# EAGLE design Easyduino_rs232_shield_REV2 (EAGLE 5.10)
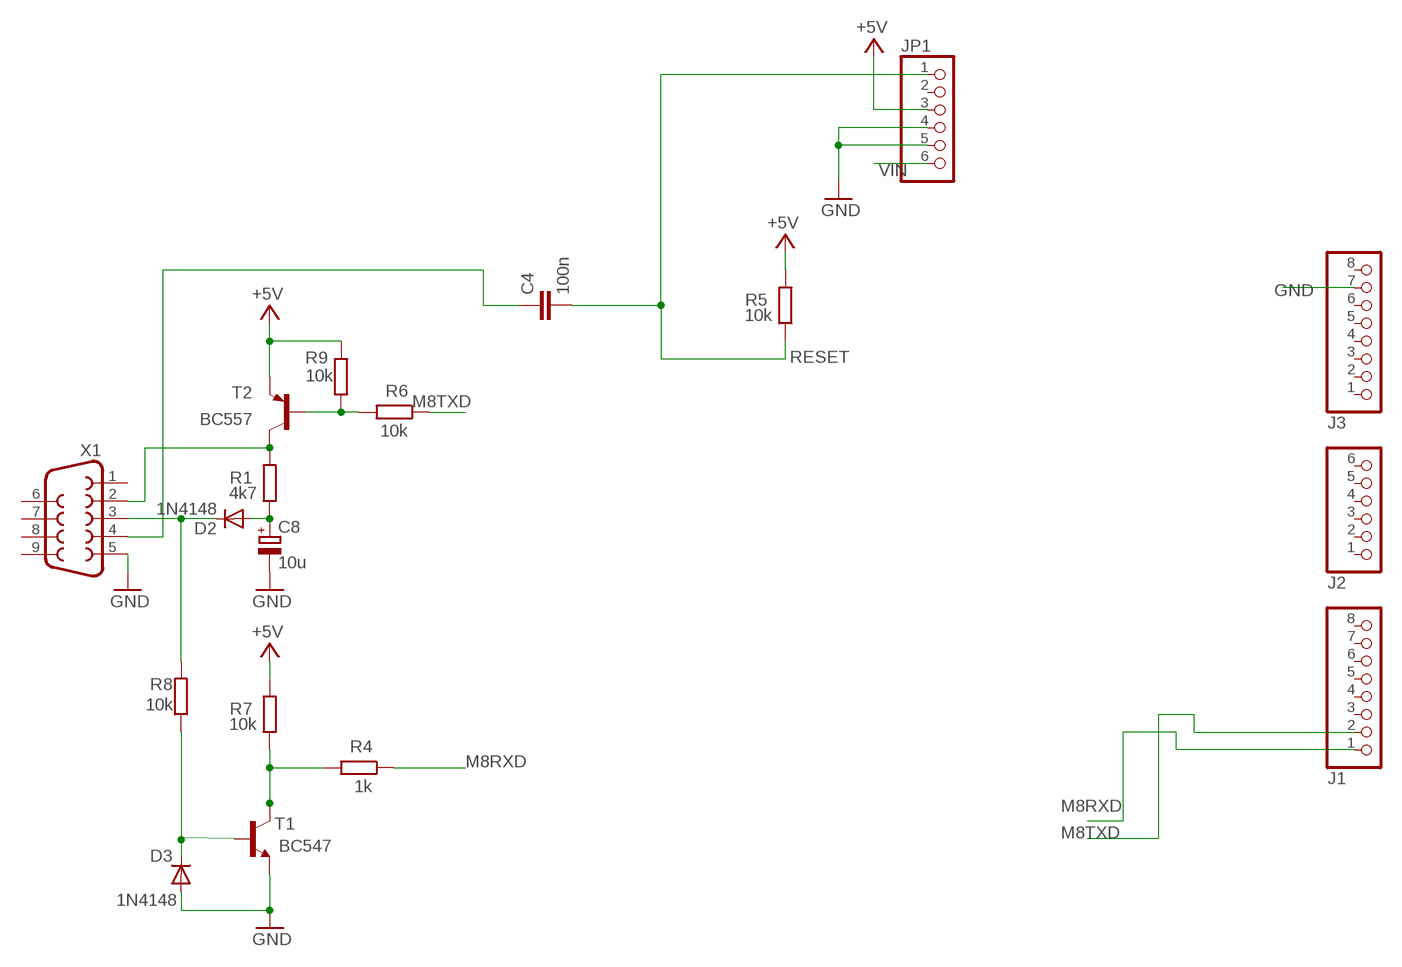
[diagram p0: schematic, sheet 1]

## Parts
C4  100n  C-EU050-025X075  [C050-025X075]
C8  10u  CPOL-EUE5-6  [E5-6]
D2  1N4148  [DO35-10]
D3  1N4148  [DO35-10]
J1  PINHD-1X8  [1X08]
J2  PINHD-1X6  [1X06]
J3  PINHD-1X8  [1X08]
JP1  PINHD-1X6  [1X06]
R1  4k7  R-EU_0207/10  [0207/10]
R4  1k  R-EU_0207/10  [0207/10]
R5  10k  R-EU_0207/10  [0207/10]
R6  10k  R-EU_0207/10  [0207/10]
R7  10k  R-EU_0207/10  [0207/10]
R8  10k  R-EU_0207/10  [0207/10]
R9  10k  R-EU_0207/10  [0207/10]
T1  BC547  [TO92]
T2  BC557  BC557B-PNP-TO92-EBC  [TO92-EBC]
X1  F09H  [F09H]

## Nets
+5V [power]: JP1.3 R5.2 R7.2 R9.1 T2.E
GND [power]: C8.- D3.A J3.7 JP1.4 JP1.5 T1.1(E) X1.5
M8RXD: J1.1 R4.1
M8TXD: J1.2 R6.1
N$9: R1.2 T2.C X1.2
N$24: C8.+ D2.A R1.1
N$25: D2.C R8.2 X1.3
N$26: R4.2 R7.1 T1.3(C)
N$27: R6.2 R9.2 T2.B
N$28: C4.1 X1.4
N$29: D3.C R8.1 T1.2(B)
RESET: C4.2 JP1.1 R5.1
VIN [power]: JP1.6
Unconnected: J1.3 J1.4 J1.5 J1.6 J1.7 J1.8 J2.1 J2.2 J2.3 J2.4 J2.5 J2.6 J3.1 J3.2 J3.3 J3.4 J3.5 J3.6 J3.8 JP1.2 X1.1 X1.6 X1.7 X1.8 X1.9

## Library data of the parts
C4 = rcl:C-EU: CAPACITOR, European symbol
C8 = rcl:CPOL-EU: POLARIZED CAPACITOR, European symbol
D2 D3 = diode:1N4148: DIODE
J1 J3 = pinhead:PINHD-1X8: PIN HEADER
J2 JP1 = pinhead:PINHD-1X6: PIN HEADER
R1 R4-R9 = rcl:R-EU_: RESISTOR, European symbol
T1 = transistor:BC547: NPN TRANSISTOR
T2 = transistor:*-PNP-: PNP Transistror
X1 = con-subd:F09: SUB-D

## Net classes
1 power: width 0.61 mm

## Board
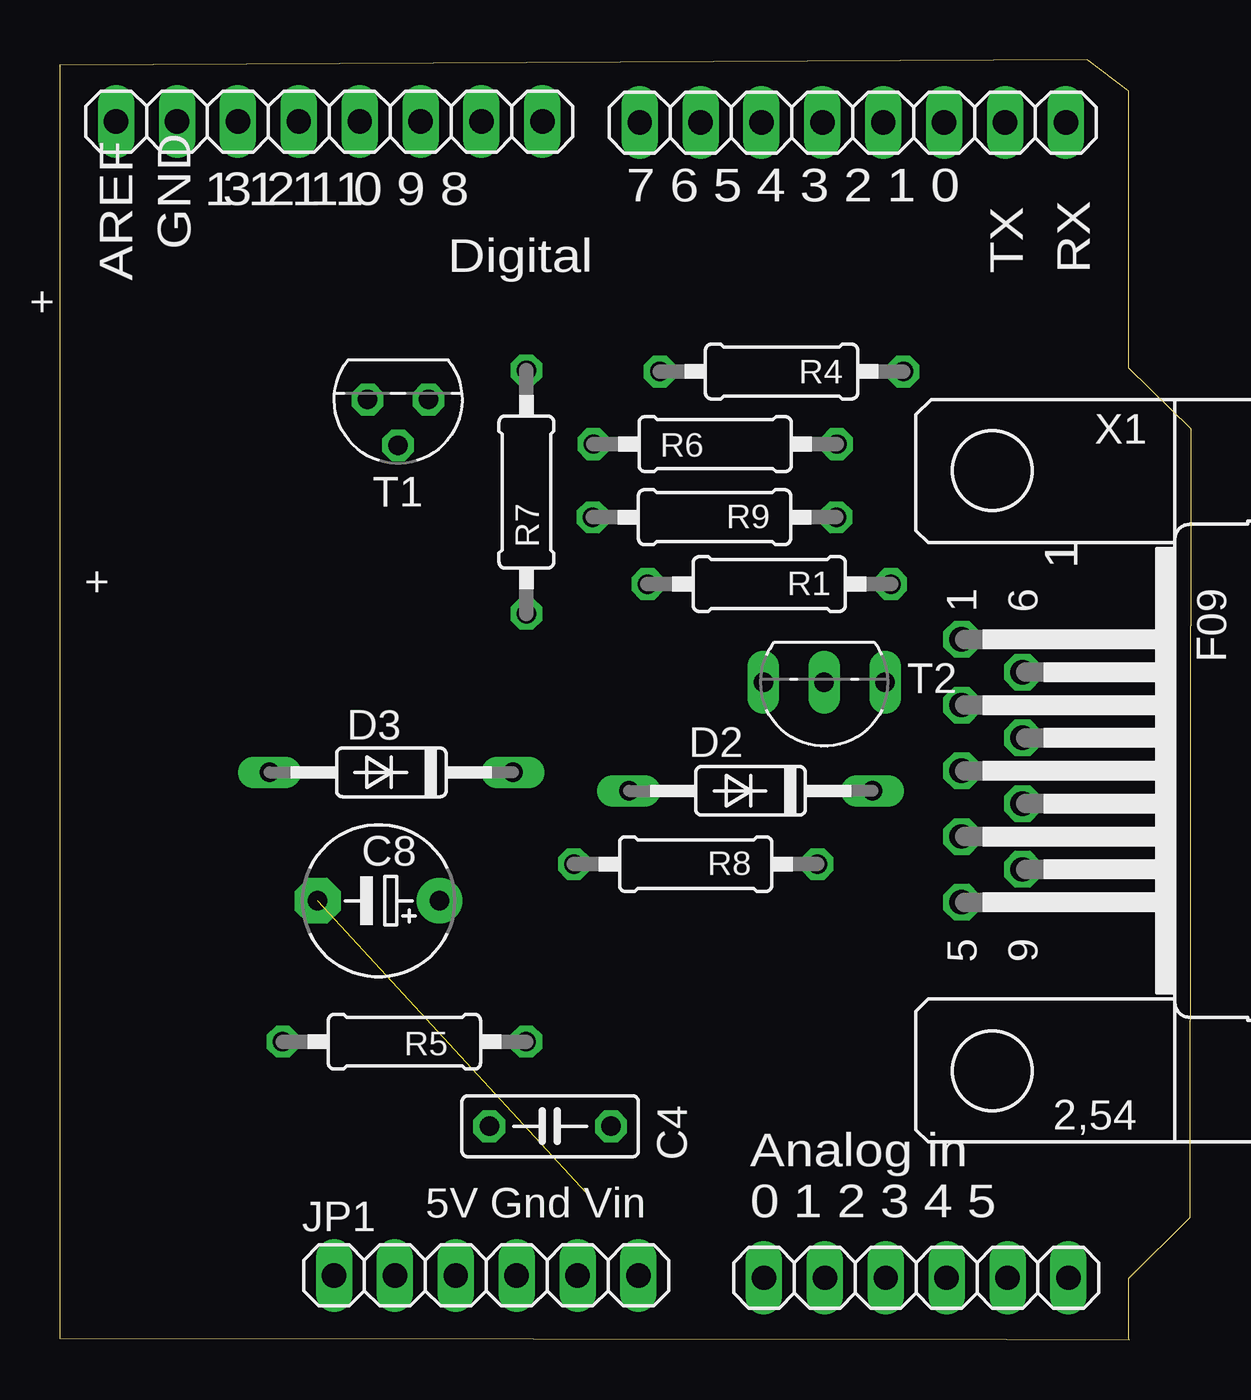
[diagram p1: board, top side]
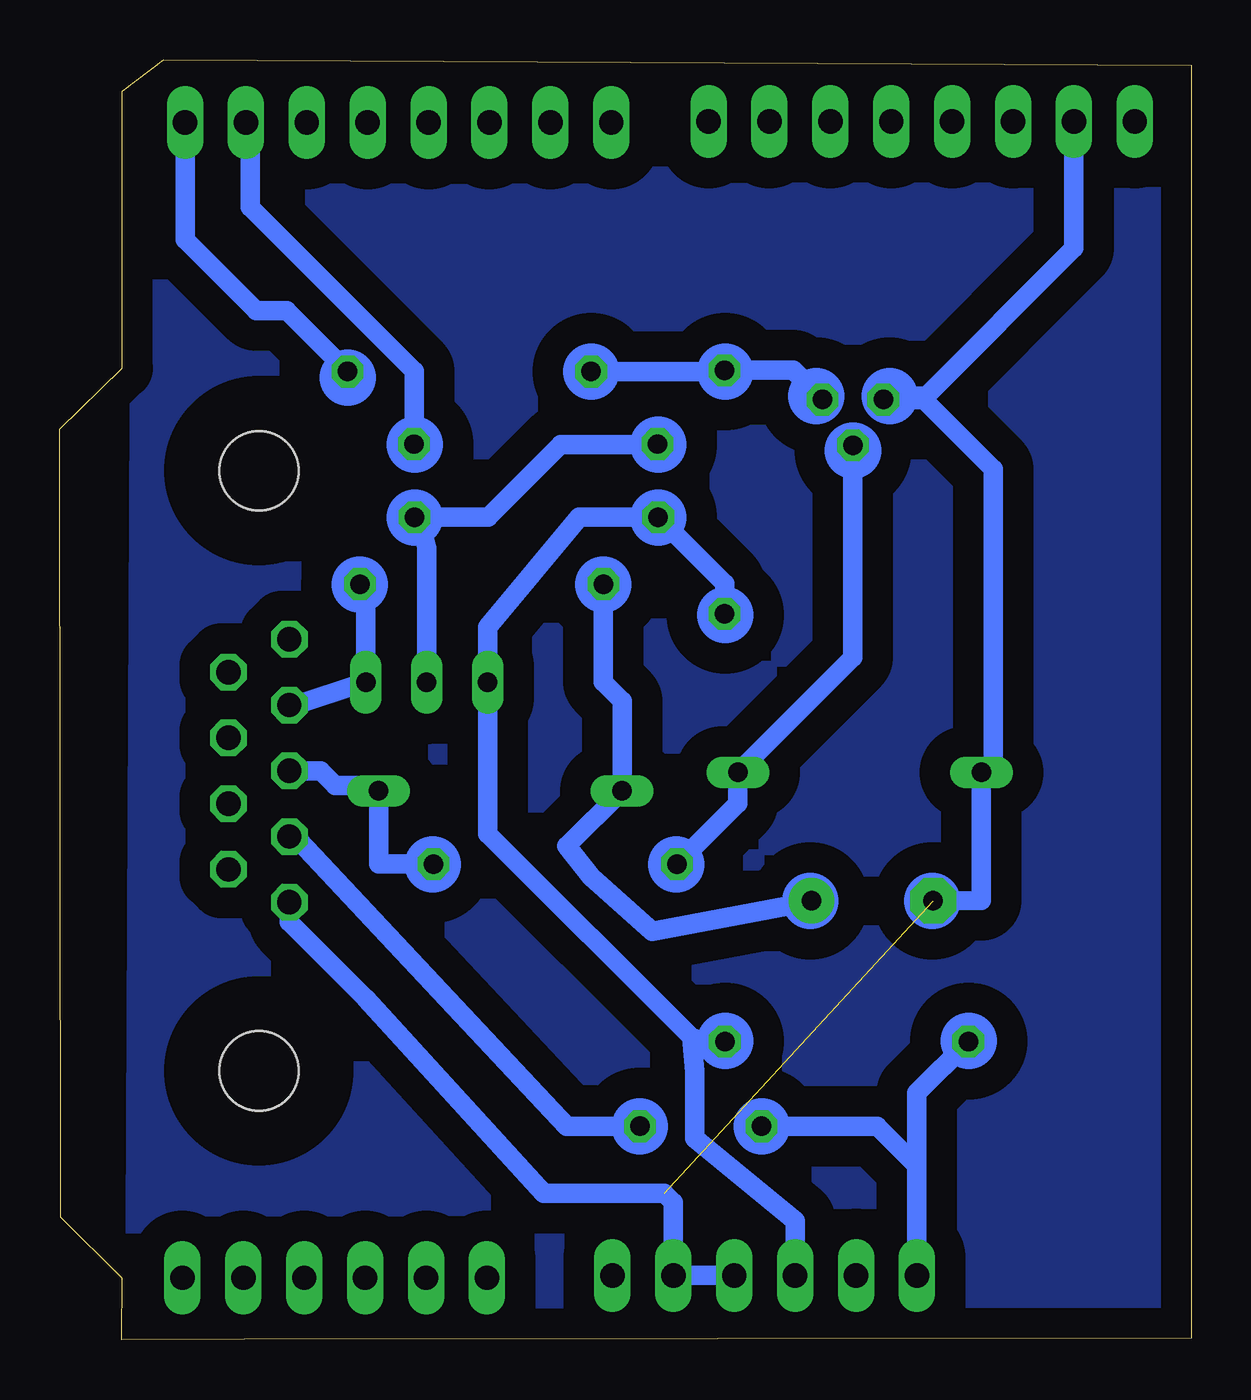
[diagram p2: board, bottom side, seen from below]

Size 47.18 x 53.4 mm. Coordinates in mm from the lower left corner, seen from the top.
Outline: 0,53.19 0,0.05 39.5,0.01 44.6,0 44.6,0.05 44.58,2.55 47.16,5.11 47.18,38 44.58,40.54 44.58,52.1 42.85,53.4 0,53.19
Copper layers (1*16): Top 0.035mm / dielectric 1.5mm / Bottom 0.035mm
Design rules "default": minimum track width 10mil, minimum drill 24mil, track to track 8mil, track to pad 8mil, pad to pad 8mil, via to via 8mil, smd to smd 8mil, copper to edge 40mil, drill to drill 8mil, minimum pad ring 10mil, minimum via ring 8mil, stop-mask expansion 4mil, vias tented up to drill 0mil, thermal gap 10mil

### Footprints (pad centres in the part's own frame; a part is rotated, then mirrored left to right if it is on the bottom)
C050-025X075 = drill 0.813 octagon: 1 -2.54,0; 2 2.54,0
E5-6 = drill 0.813 pad 1.905 round: + -2.54,0 | drill 0.813 pad 1.905 octagon: - 2.54,0
DO35-10 = drill 0.813 long: A 5.08,0; C -5.08,0
1X08 = drill 1.016 long: 1 -8.89,0; 2 -6.35,0; 3 -3.81,0; 4 -1.27,0; 5 1.27,0; 6 3.81,0; 7 6.35,0; 8 8.89,0
1X06 = drill 1.016 long: 1 -6.35,0; 2 -3.81,0; 3 -1.27,0; 4 1.27,0; 5 3.81,0; 6 6.35,0
0207/10 = drill 0.813 octagon: 1 -5.08,0; 2 5.08,0
TO92 = drill 0.813 octagon: 1 1.27,0; 2 0,1.905; 3 -1.27,0
TO92-EBC = drill 0.813 long: B 0,-1.27; C -2.54,-1.27; E 2.54,-1.27
F09H = drill 1.016 octagon: 1 -5.486,-1.27; 2 -2.743,-1.27; 3 0,-1.27; 4 2.743,-1.27; 5 5.486,-1.27; 6 -4.115,1.27; 7 -1.372,1.27; 8 1.372,1.27; 9 4.115,1.27 | hole 3.302: -12.522,0; 12.522,0

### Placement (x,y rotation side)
C4  20.45,8.9 180 top
C8  13.29,18.31 180 top
D2  28.81,22.9 180 top
D3  13.82,23.67 180 top
J1  33.08,50.79 180 top
J2  35.72,2.58 0 top
J3  11.23,50.83 180 top
JP1  17.78,2.68 0 top
R1  29.59,31.53 0 top
R4  30.1,40.4 180 top
R5  14.37,12.43 0 top
R6  27.33,37.37 180 top
R7  19.46,35.37 270 top
R8  26.52,19.84 0 top
R9  27.31,34.32 0 top
T1  14.11,39.23 180 top
T2  31.88,26.16 180 top
X1  38.89,23.74 270 top

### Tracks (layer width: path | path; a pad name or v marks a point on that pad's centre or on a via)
+5V
  Bottom 0.813: JP1.3 16.51,4.96 20.7,8.39 20.7,11.19 20.83,12.61 | 20.83,12.61 29.34,21.09 29.34,26.42 T2.E 29.34,26.42 29.34,29.73 25.51,34.32 R9.1 19.46,31.55 R7.2 | R5.2 20.25,12.43 20.83,12.61
GND  (1 unrouted)
  Bottom 0.813: X1.5 37.62,17.43 34.42,14.23 27,6.11 21.97,6.11 21.59,5.73 JP1.5 JP1.4 | J3.7 4.88,45.55 11.05,39.38 12.68,39.38 T1.1 11.15,39.23 8.26,36.33 8.26,24.16 D3.A 8.74,18.32 9.78,18.3 10.74,18.3 C8.-
M8RXD
  Bottom 0.813: J1.1 41.97,45.91 38.99,42.94 37.72,42.94 R4.1
M8TXD
  Bottom 0.813: R6.1 32.41,40.42 39.25,47.25 39.25,50.61 J1.2
N$1
  pour Bottom (isolate 1.27): 1.4,0.52 1.4,52.84 42.29,52.59 43.31,51.57 43.82,51.57 44.07,0.52
N$9
  Bottom 0.813: X1.2 37.55,26.42 T2.C 34.42,31.01 R1.2
N$24
  Bottom 0.813: R1.1 24.51,27.44 23.73,26.66 D2.A 26.04,20.59 25.02,19.31 22.48,17.03 15.92,18.25 C8.+
N$25
  Bottom 0.813: X1.3 36.3,23.74 35.69,23.12 34.11,23.12 D2.C 33.89,19.84 R8.2
N$26
  Bottom 0.813: R4.2 19.51,40.4 R7.1 16.6,40.45 T1.3
N$27
  Bottom 0.813: T2.B 31.88,32.78 31.88,33.03 32.14,34.06 R9.2 29.32,34.32 26.29,37.35 22.27,37.35 R6.2
N$28
  Bottom 0.813: C4.1 26.04,8.9 37.21,20.84 37.46,21.09 X1.4
N$29
  Bottom 0.813: T1.2 14.11,28.47 D3.C 18.9,22.38 R8.1
RESET
  Bottom 0.813: R5.1 11.43,10.29 JP1.1 11.43,7.25 13.08,8.9 C4.2
(copper drawn outside any net)
  shapes: Bottom circle x21

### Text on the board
tNames: 1 1 1 1 | 3 2 1 0 9 8 | 7 6 5 4 3 2 1 0 | GND | Digital | AREF | TX | RX | + | 1 | + | Analog in | 5V Gnd Vin | 0 1 2 3 4 5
